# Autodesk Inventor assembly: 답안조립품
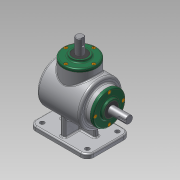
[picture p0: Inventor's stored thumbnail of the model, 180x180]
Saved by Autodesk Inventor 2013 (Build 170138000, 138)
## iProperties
Created: 2016-09
Part Number: 답안조립품
Document SubType Name: Assembly
Designer: default
Author: default
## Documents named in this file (14)
- C:\Documents and Settings\default\바탕 화면\460908V1011\답안조립품.iam
- C:\Documents and Settings\default\바탕 화면\460908V1011\1.본체.ipt
- C:\Documents and Settings\default\바탕 화면\460908V1011\커버.ipt
- C:\Documents and Settings\default\바탕 화면\460908V1011\오일실 17 32 8.ipt
- C:\Documents and Settings\default\바탕 화면\460908V1011\베어링 6203.ipt
- C:\Documents and Settings\default\바탕 화면\460908V1011\M4.ipt
- C:\Documents and Settings\default\바탕 화면\460908V1011\메인 축.ipt
- 메인 축.ipt
- C:\Documents and Settings\default\바탕 화면\460908V1011\서브 축.ipt
- 서브 축.ipt
- C:\Documents and Settings\default\바탕 화면\460908V1011\서브 베벨기어.ipt
- C:\Documents and Settings\default\바탕 화면\460908V1011\메인 베벨기어.ipt
- C:\Documents and Settings\default\바탕 화면\460908V1011\키 4x4.ipt
- C:\Documents and Settings\default\바탕 화면\460908V1011\키 5x5.ipt
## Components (9 placed, 2 different names)
1. 1.본체:1
2. M4:1
3. M4:3
4. M4:4
5. M4:5
6. M4:2
7. M4:6
8. M4:7
9. M4:8
